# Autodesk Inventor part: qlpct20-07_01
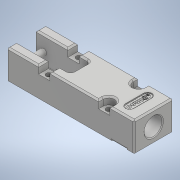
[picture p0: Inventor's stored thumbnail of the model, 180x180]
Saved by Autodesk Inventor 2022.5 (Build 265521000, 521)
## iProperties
Part Number: qlpct20-07_01
Material: 一般
Document SubType Name: Modeling
Designer: ImaoCorp
Density: 1 g/cm^3
Appearance: 既定
Author: ImaoCorp
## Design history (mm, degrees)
feature "qlpct20-07_01"
node "ソリッド1"
